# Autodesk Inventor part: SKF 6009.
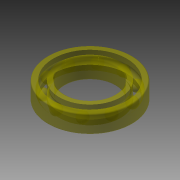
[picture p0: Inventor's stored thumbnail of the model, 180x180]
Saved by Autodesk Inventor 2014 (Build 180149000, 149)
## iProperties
Created: 2001-01
Part Number: SKF 6009.
Material: Steel, Mild
Description: Bearing SKF 6009.
Document SubType Name: Modeling
Density: 7.86 g/cm^3
Appearance: Yellow(Clear)
ProtocolID: P00020917123444006
Protocol: P00020917123444006<@PID>[Version]<@EL>Version=2.2<@EL>[Synchronize]<@EL>ChangedVars=<@EL>[Calc]<@EL>CalcName=BEARINGS<@EL>Optim=1<@EL>WizardMode=2<@EL>ScnVisibl
Control State: 0
Master: False
Checked Out: False
Shininess: 20.0
Length Units: 11269
Angle Units: 11279
Time Units: 11290
Mass Units: 11283
Length Display Precision: 3
Angle Display Precision: 2
BOM1: Bearing
BOM2: SKF 6009
Density: 7.86
Volumn: 47.63899704516156
Area: 199.2492810037185
PropertySet Name: Model Information
Author: PaulN
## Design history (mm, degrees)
node "Sketch1"
node "WorkPoint1"
sketch "Sketch2"
  geometry: L1 (22.5, 16)-(37.5, 16); L2 (22.5, 0)-(22.5, 16); L3 (37.5, 0)-(22.5, 0); L4 (37.5, 16)-(37.5, 0); L5 (0, 0)-(0, 20); L6 (0, 0)-(0, 20); L7 (-7.5, 0)-(45, 0) reference
  constraints: 12 end point, 3 vertical, 2 horizontal, 1 collinear, 1 other
  dimensions: "d1" = 45 diameter of L1.start L5 (= prf_d); "d3" = 75 diameter of L1.end L5 (= prf_dd); "d5" = 16 distance of L2.start L1.start (= msp_mdtd2)
revolve "RevolutionFull1" sketch "Sketch2" stored, may be unused: angle "d6" = 360 deg
node "WorkAxis1"
node "WorkPlane3"
sketch "Sketch3"
  geometry: L1 (32.7, 16)-(32.7, 11.6); L2 (27.3, 16)-(32.7, 16); L3 (27.3, 11.6)-(27.3, 16); L4 (27.3, 0)-(27.3, 4.4); L5 (32.7, 0)-(27.3, 0); L6 (32.7, 4.4)-(32.7, 0); L7 (37.5, 0)-(-37.5, 0) reference; L8 (37.5, 16)-(-37.5, 16) reference; L9 (0, -42.29)-(0, 61.29); L10 (0, 82.007)-(0, -63.007) reference; A1 r 4.5 centre (30, 8) between (32.7, 4.4) and (32.7, 11.6); A2 r 4.5 centre (30, 8) between (27.3, 11.6) and (27.3, 4.4)
  constraints: 14 end point, 4 collinear, 4 point on circle, 4 vertical, 2 centre point, 2 concentric, 2 horizontal, 2 point on line
  dimensions: "d9" = 9 diameter of A1 (= msp_mdtd6); "d21" = 27.3 distance between parallel lines of L9 L4 (= 0.5 x msp_d1); "d22" = 30 distance from line of L9 A1.centre (= 0.5 x msp_ds); "d23" = 32.7 distance between parallel lines of L9 L6 (= 0.5 x msp_dd1)
revolve "RevolutionFull2" sketch "Sketch3" stored, may be unused: angle "d10" = 360 deg
node "WorkPlane4"
node "Sketch4"
node "WorkPoint2"
sketch "Sketch5"
  geometry: L1 (30, 3.5)-(30, 12.5); L2 (32.7, 0)-(-32.7, 0) reference; L3 (30, 3.5)-(30, 12.5); A1 r 4.5 centre (30, 8) between (30, 3.5) and (30, 12.5); A2 r 4.5 centre (30, 8) between (32.7, 4.4) and (32.7, 11.6) reference
  constraints: 4 end point, 2 point on circle, 1 centre point, 1 concentric, 1 vertical
  dimensions: "d13" = 0 horizontal distance of A1.centre L1.start; "d15" = 9.0001 diameter of A1 (computed from msp_mdtd6)
revolve "RevolutionFull3" sketch "Sketch5" stored, may be unused: angle "d16" = 360 deg
pattern_circular "PolarAray1" dims "d17" = 104 (= msp_pocet), angle "d19" = 360 deg
fillet "Fillet1" dims "d20" = 1 (= prf_r)
body "Solid1"
other parameters: "prf_d" = 45 [user parameter; used in 3 equation terms], "prf_dd" = 75 [user parameter; used in 3 equation terms], "prf_b" = 16 [user parameter; used in 1 equation term], "prf_r" = 1 [user parameter; used in 1 equation term], "msp_d0" = 9 (= -0.3 x prf_d + 0.3 x prf_dd) [user parameter; used in 4 equation terms], "msp_d1" = 54.6 (= msp_ds - 0.6 x msp_d0) [user parameter; used in 1 equation term], "msp_dd1" = 65.4 (= msp_ds + 0.6 x msp_d0) [user parameter; used in 1 equation term], "msp_mdtd2" = 16 (= prf_b) [user parameter; used in 3 equation terms], "msp_mdtd6" = 9 (= msp_d0) [user parameter; used in 2 equation terms], "msp_mdtd7" = 8 (= 0.5 x msp_mdtd2) [user parameter], "msp_pocet" = 104 (computed from msp_d0, msp_pom) [user parameter; used in 1 equation term], "d2" = 72 (derived), "d4" = 19 (derived), "d7" = 0, "d8" = 15.6 (derived), "d11" = -16 (computed from msp_mdtd2), "d12" = 0 (derived), "d14" = 15.6001 (derived), "d25" = 0
